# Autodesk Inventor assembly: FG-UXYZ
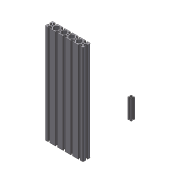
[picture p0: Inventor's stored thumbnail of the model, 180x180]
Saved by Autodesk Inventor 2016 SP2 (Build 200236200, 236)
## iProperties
Created: 2017-11
Part Number: FG-UXYZ
Document SubType Name: Assembly
Designer: compassadm
MT_KOPF: =<CPR_ZEICHNR> - <CPR_SHORT>
Author: compassadm
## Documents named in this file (7)
- C:\Vault\Inventor\Produkt Daten\FG-UXYZ.iam
- C:\Vault\Vorlagen\iParts\Item\01 - Grundelemente\03 - Zubehör Profile\0.0.370.09 - Abdeckkappe 5 20x20\IPT_0.0.370.09.ipt
- C:\Vault\Vorlagen\iParts\Item\01 - Grundelemente\03 - Zubehör Profile\0.0.370.09.ipt
- C:\Vault\Inventor\Produkt Daten\200x40.ipt
- C:\Vault\Vorlagen\iParts\Item\01 - Grundelemente\01 - Profile\03 - Profile 08\0.0.473.82.ipt
- C:\Vault\Inventor\Produkt Daten\FG-UXYZ_hz\0.0.370.03_100,000CAD-ZB-125BGCA34.ipt
- C:\Vault\Vorlagen\iParts\Item\01 - Grundelemente\01 - Profile\01 - Profile 05\0.0.370.03.ipt
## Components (3 placed, 2 different names)
1. -:1
2. -:1
3. 0.0.370.03 - 100,000:1
